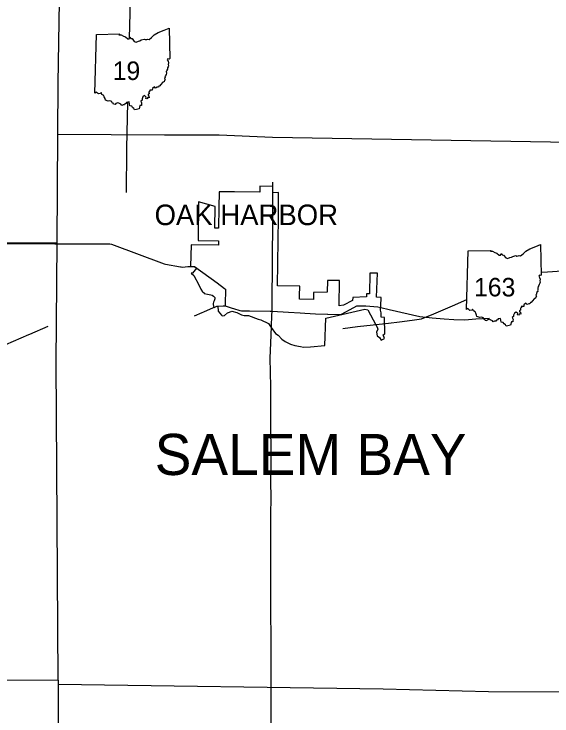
# Model space of a CAD drawing. Extents: x -232 to 448, y 619 to 1059.
# Drawn here: x 271.78 to 298.62, y 854.99 to 890 of the extents above; entities that cross this region are included whole.
import ezdxf

# ---------------------------------------------------------------- set-up
doc = ezdxf.new("R2010")
doc.units = 0
doc.layers.add('Default', color=7, linetype='Continuous')

msp = doc.modelspace()

# ---------------------------------------------------------------- linework, layer by layer
at = {"layer": 'Default'}
for p, q in [((275.817, 886.053), (275.899, 888.982)), ((275.817, 886.053), (275.899, 888.982)), ((284.048, 881.405), (284.047, 881.111)), ((284.697, 881.399), (284.048, 881.405)), ((280.977, 880.636), (280.973, 878.696)), ((281.81, 880.401), (280.977, 880.636)), ((281.804, 879.324), (281.81, 880.401)), ((281.986, 879.323), (281.804, 879.324)), ((280.973, 878.696), (281.983, 878.692)), ((280.621, 878.48), (280.591, 877.406)), ((294.349, 875.26), (294.431, 878.189)), ((294.349, 875.26), (294.431, 878.189)), ((280.891, 877.328), (280.692, 877.07))]:
    msp.add_line(p, q, dxfattribs=at)
for points in [[(273.973, 884.01), (273.991, 886.54), (274.111, 894.733), (274.2, 900.175), (274.21, 900.311), (274.401, 911.082), (274.524, 918.377)], [(277.536, 888.796), (277.606, 891.306), (277.607, 891.375), (277.67, 896.738), (277.671, 896.823), (277.644, 899.424), (277.643, 899.47)], [(275.899, 888.982), (277.036, 889.001), (277.018, 888.966), (277.125, 888.958), (277.239, 888.896), (277.335, 888.856), (277.453, 888.763), (277.524, 888.764), (277.554, 888.84), (277.608, 888.781), (277.672, 888.771), (277.782, 888.631), (277.874, 888.6), (277.983, 888.648), (278.065, 888.656), (278.125, 888.704), (278.281, 888.744), (278.325, 888.72), (278.407, 888.725), (278.449, 888.743), (278.521, 888.727), (278.647, 888.833), (278.778, 888.959), (278.979, 889.077), (279.278, 889.19), (279.515, 889.29), (279.55, 887.77)], [(275.899, 888.982), (277.036, 889.001), (277.018, 888.966), (277.125, 888.958), (277.239, 888.896), (277.335, 888.856), (277.453, 888.763), (277.524, 888.764), (277.554, 888.84), (277.608, 888.781), (277.672, 888.771), (277.782, 888.631), (277.874, 888.6), (277.983, 888.648), (278.065, 888.656), (278.125, 888.704), (278.281, 888.744), (278.325, 888.72), (278.407, 888.725), (278.449, 888.743), (278.521, 888.727), (278.647, 888.833), (278.778, 888.959), (278.979, 889.077), (279.278, 889.19), (279.515, 889.29), (279.55, 887.77)], [(279.55, 887.77), (279.515, 887.749), (279.46, 887.759), (279.424, 887.716), (279.469, 887.645), (279.49, 887.57), (279.471, 887.487), (279.49, 887.419), (279.477, 887.362), (279.443, 887.305), (279.431, 887.25), (279.402, 887.193), (279.405, 887.161), (279.377, 887.136), (279.382, 887.041), (279.368, 886.988), (279.373, 886.943), (279.328, 886.931), (279.338, 886.893), (279.309, 886.864), (279.315, 886.814), (279.283, 886.783), (279.315, 886.719), (279.289, 886.699), (279.268, 886.621), (279.211, 886.605), (279.095, 886.464), (279.054, 886.41), (279.008, 886.397), (278.983, 886.341), (278.927, 886.341), (278.841, 886.303), (278.786, 886.369), (278.689, 886.29), (278.678, 886.198), (278.556, 886.201), (278.561, 886.155), (278.534, 886.142), (278.509, 886.095), (278.523, 886.013), (278.466, 885.992), (278.473, 885.945), (278.51, 885.915), (278.526, 885.824), (278.465, 885.843), (278.415, 885.766), (278.364, 885.784), (278.381, 885.849), (278.294, 885.927), (278.212, 885.865), (278.17, 885.764), (278.169, 885.697), (278.108, 885.656), (278.147, 885.561), (278.14, 885.495), (278.141, 885.433), (278.065, 885.435), (278.019, 885.267)], [(279.55, 887.77), (279.515, 887.749), (279.46, 887.759), (279.424, 887.716), (279.469, 887.645), (279.49, 887.57), (279.471, 887.487), (279.49, 887.419), (279.477, 887.362), (279.443, 887.305), (279.431, 887.25), (279.402, 887.193), (279.405, 887.161), (279.377, 887.136), (279.382, 887.041), (279.368, 886.988), (279.373, 886.943), (279.328, 886.931), (279.338, 886.893), (279.309, 886.864), (279.315, 886.814), (279.283, 886.783), (279.315, 886.719), (279.289, 886.699), (279.268, 886.621), (279.211, 886.605), (279.095, 886.464), (279.054, 886.41), (279.008, 886.397), (278.983, 886.341), (278.927, 886.341), (278.841, 886.303), (278.786, 886.369), (278.689, 886.29), (278.678, 886.198), (278.556, 886.201), (278.561, 886.155), (278.534, 886.142), (278.509, 886.095), (278.523, 886.013), (278.466, 885.992), (278.473, 885.945), (278.51, 885.915), (278.526, 885.824), (278.465, 885.843), (278.415, 885.766), (278.364, 885.784), (278.381, 885.849), (278.294, 885.927), (278.212, 885.865), (278.17, 885.764), (278.169, 885.697), (278.108, 885.656), (278.147, 885.561), (278.14, 885.495), (278.141, 885.433), (278.065, 885.435), (278.019, 885.267)], [(278.019, 885.267), (277.886, 885.235), (277.794, 885.216), (277.762, 885.292), (277.696, 885.332), (277.653, 885.409), (277.558, 885.42), (277.536, 885.525), (277.525, 885.611), (277.396, 885.59), (277.361, 885.537), (277.315, 885.523), (277.288, 885.471), (277.226, 885.466), (277.159, 885.441), (277.115, 885.493), (277.005, 885.545), (276.956, 885.572), (276.852, 885.53), (276.83, 885.481), (276.748, 885.503), (276.729, 885.558), (276.679, 885.574), (276.668, 885.632), (276.562, 885.664), (276.48, 885.651), (276.337, 885.698), (276.328, 885.775), (276.279, 885.868), (276.254, 885.933), (276.163, 885.983), (276.145, 886.06), (276.116, 886.058), (276.089, 886.027), (275.988, 886.012), (275.948, 886.044), (275.892, 886.098), (275.817, 886.053)], [(278.019, 885.267), (277.886, 885.235), (277.794, 885.216), (277.762, 885.292), (277.696, 885.332), (277.653, 885.409), (277.558, 885.42), (277.536, 885.525), (277.525, 885.611), (277.396, 885.59), (277.361, 885.537), (277.315, 885.523), (277.288, 885.471), (277.226, 885.466), (277.159, 885.441), (277.115, 885.493), (277.005, 885.545), (276.956, 885.572), (276.852, 885.53), (276.83, 885.481), (276.748, 885.503), (276.729, 885.558), (276.679, 885.574), (276.668, 885.632), (276.562, 885.664), (276.48, 885.651), (276.337, 885.698), (276.328, 885.775), (276.279, 885.868), (276.254, 885.933), (276.163, 885.983), (276.145, 886.06), (276.116, 886.058), (276.089, 886.027), (275.988, 886.012), (275.948, 886.044), (275.892, 886.098), (275.817, 886.053)], [(277.398, 881.098), (277.41, 883.221), (277.41, 883.292), (277.452, 885.599)], [(273.933, 878.589), (273.973, 884.01)], [(273.973, 884.01), (279.293, 883.973), (282.013, 883.967), (284.683, 883.859), (306.452, 883.484)], [(284.698, 881.398), (284.699, 881.614)], [(282.023, 881.125), (281.995, 880.342)], [(282.777, 881.122), (282.023, 881.125)], [(284.047, 881.111), (282.777, 881.122)], [(284.689, 879.832), (284.689, 879.837), (284.696, 881.128)], [(284.928, 876.433), (284.979, 879.831), (284.977, 881.1), (284.696, 881.083), (284.697, 881.399)], [(284.696, 881.128), (284.698, 881.398)], [(281.995, 880.342), (281.986, 879.323)], [(284.66, 875.561), (284.689, 879.733), (284.689, 879.832)], [(240.982, 878.692), (246.674, 878.656), (273.933, 878.589)], [(281.983, 878.692), (281.982, 878.474)], [(268.435, 878.575), (268.462, 878.574), (273.825, 878.539), (273.836, 878.539)], [(273.836, 878.539), (273.911, 878.537), (276.565, 878.528), (276.639, 878.527), (279.278, 877.542), (279.333, 877.521), (280.08, 877.393), (280.125, 877.385)], [(273.979, 856.774), (273.889, 872.62), (273.933, 878.589)], [(281.982, 878.474), (280.621, 878.48)], [(294.431, 878.189), (295.567, 878.208), (295.549, 878.173), (295.657, 878.165), (295.77, 878.103), (295.867, 878.063), (295.985, 877.97), (296.055, 877.971), (296.085, 878.048), (296.139, 877.989), (296.203, 877.978), (296.314, 877.838), (296.405, 877.808), (296.515, 877.856), (296.597, 877.864), (296.656, 877.911), (296.812, 877.952), (296.856, 877.927), (296.938, 877.932), (296.98, 877.95), (297.052, 877.934), (297.179, 878.041), (297.309, 878.166), (297.51, 878.285), (297.81, 878.397), (298.047, 878.497), (298.081, 876.977)], [(294.431, 878.189), (295.567, 878.208), (295.549, 878.173), (295.657, 878.165), (295.77, 878.103), (295.867, 878.063), (295.985, 877.97), (296.055, 877.971), (296.085, 878.048), (296.139, 877.989), (296.203, 877.978), (296.314, 877.838), (296.405, 877.808), (296.515, 877.856), (296.597, 877.864), (296.656, 877.911), (296.812, 877.952), (296.856, 877.927), (296.938, 877.932), (296.98, 877.95), (297.052, 877.934), (297.179, 878.041), (297.309, 878.166), (297.51, 878.285), (297.81, 878.397), (298.047, 878.497), (298.081, 876.977)], [(298.078, 877.118), (298.397, 877.137), (299.601, 877.224), (300.965, 877.397), (301.903, 877.516), (303.294, 877.506), (305.081, 877.449), (305.907, 877.436), (306.891, 877.597), (308.158, 877.77), (309.088, 877.934), (309.866, 878.062), (310.944, 878.031), (312.431, 877.934), (313.078, 877.869), (313.147, 877.862), (313.956, 877.943), (314.053, 877.953), (315.885, 878.144), (315.952, 878.15), (317.947, 878.338), (317.947, 878.338), (318.038, 878.346)], [(280.125, 877.385), (280.18, 877.375), (280.445, 877.398)], [(280.445, 877.398), (280.45, 877.399), (280.536, 877.406), (280.699, 877.405), (280.787, 877.404), (281.908, 876.584)], [(280.591, 877.406), (280.787, 877.404)], [(280.787, 877.404), (280.891, 877.328)], [(280.692, 877.07), (280.662, 877.08), (280.658, 877.078), (280.62, 877.08)], [(280.62, 877.08), (280.754, 876.959)], [(280.754, 876.959), (280.997, 876.492), (281.103, 876.271), (281.187, 876.147), (281.205, 876.124), (281.255, 876.107)], [(289.284, 875.273), (289.428, 875.236), (289.832, 874.496), (289.889, 874.379), (289.934, 874.278), (289.857, 874.134), (289.899, 873.947), (290.018, 873.866), (290.101, 873.732), (290.256, 873.817), (290.191, 873.997), (290.28, 874.048), (290.261, 874.858), (290.091, 874.88), (290.096, 875.1), (290.055, 875.228), (290.077, 875.452), (290.101, 875.865), (289.865, 875.874), (289.905, 877.074), (289.529, 877.073), (289.514, 876.038), (289.368, 876.049), (289.359, 875.885), (288.677, 875.867), (288.67, 875.713), (288.225, 875.478), (287.995, 875.45), (288.013, 876.705), (287.415, 876.702), (287.407, 876.129)], [(298.081, 876.977), (298.046, 876.956), (297.992, 876.966), (297.955, 876.923), (298, 876.852), (298.022, 876.777), (298.003, 876.694), (298.021, 876.626), (298.009, 876.569), (297.974, 876.512), (297.963, 876.458), (297.934, 876.401), (297.936, 876.369), (297.908, 876.343), (297.913, 876.248), (297.899, 876.196), (297.904, 876.15), (297.859, 876.138), (297.869, 876.101), (297.841, 876.072), (297.847, 876.022), (297.814, 875.99), (297.846, 875.926), (297.821, 875.906), (297.8, 875.828), (297.742, 875.813), (297.626, 875.671), (297.585, 875.617), (297.54, 875.604), (297.514, 875.549), (297.458, 875.548), (297.373, 875.51), (297.318, 875.576), (297.221, 875.497), (297.21, 875.406), (297.087, 875.409), (297.092, 875.362), (297.065, 875.349), (297.04, 875.303), (297.054, 875.22), (296.997, 875.2), (297.004, 875.152), (297.041, 875.123), (297.057, 875.031), (296.996, 875.05), (296.946, 874.973), (296.895, 874.991), (296.912, 875.056), (296.825, 875.134), (296.744, 875.072), (296.701, 874.972), (296.7, 874.904), (296.639, 874.863), (296.678, 874.768), (296.671, 874.703), (296.672, 874.64), (296.596, 874.642), (296.55, 874.474)], [(298.081, 876.977), (298.046, 876.956), (297.992, 876.966), (297.955, 876.923), (298, 876.852), (298.022, 876.777), (298.003, 876.694), (298.021, 876.626), (298.009, 876.569), (297.974, 876.512), (297.963, 876.458), (297.934, 876.401), (297.936, 876.369), (297.908, 876.343), (297.913, 876.248), (297.899, 876.196), (297.904, 876.15), (297.859, 876.138), (297.869, 876.101), (297.841, 876.072), (297.847, 876.022), (297.814, 875.99), (297.846, 875.926), (297.821, 875.906), (297.8, 875.828), (297.742, 875.813), (297.626, 875.671), (297.585, 875.617), (297.54, 875.604), (297.514, 875.549), (297.458, 875.548), (297.373, 875.51), (297.318, 875.576), (297.221, 875.497), (297.21, 875.406), (297.087, 875.409), (297.092, 875.362), (297.065, 875.349), (297.04, 875.303), (297.054, 875.22), (296.997, 875.2), (297.004, 875.152), (297.041, 875.123), (297.057, 875.031), (296.996, 875.05), (296.946, 874.973), (296.895, 874.991), (296.912, 875.056), (296.825, 875.134), (296.744, 875.072), (296.701, 874.972), (296.7, 874.904), (296.639, 874.863), (296.678, 874.768), (296.671, 874.703), (296.672, 874.64), (296.596, 874.642), (296.55, 874.474)], [(281.908, 876.584), (282.274, 876.316), (282.333, 876.273), (282.314, 875.515), (282.314, 875.515), (282.312, 875.45)], [(287.407, 876.129), (286.722, 876.105), (286.727, 875.95), (286.727, 875.763), (286.028, 875.776), (286.014, 875.948), (286.038, 876.432), (284.928, 876.433)], [(281.255, 876.107), (281.271, 876.067), (281.599, 875.995), (281.66, 875.971), (281.733, 875.927), (281.79, 875.884), (281.803, 875.864), (281.791, 875.789), (281.76, 875.696), (281.729, 875.627), (281.713, 875.562), (281.715, 875.502), (281.732, 875.422), (281.763, 875.365)], [(284.649, 874.965), (284.658, 875.183), (284.66, 875.561)], [(288.186, 874.318), (288.914, 874.408), (289.696, 874.494), (290.454, 874.585), (291.017, 874.65), (291.635, 874.723), (292.101, 874.788), (292.73, 875.044), (293.662, 875.448), (294.363, 875.764)], [(280.786, 874.948), (281.168, 875.116), (281.25, 875.152), (281.73, 875.353)], [(281.73, 875.353), (281.8, 875.382), (281.894, 875.421), (281.932, 875.424)], [(281.763, 875.365), (281.894, 875.421), (281.948, 875.425), (281.958, 875.186), (282.124, 874.978), (282.167, 874.949), (282.274, 874.969), (282.427, 875.1), (282.528, 875.134), (282.643, 875.175), (282.895, 875.112), (283.127, 874.996), (283.259, 874.965), (283.485, 874.966), (283.965, 874.774), (284.1, 874.749), (284.471, 874.562), (284.608, 874.356), (284.825, 874.069), (284.952, 873.974), (285.144, 873.788), (285.31, 873.67), (285.581, 873.531), (285.79, 873.466), (286.078, 873.414), (286.228, 873.39), (286.575, 873.405), (287.285, 873.458)], [(281.932, 875.424), (282.219, 875.444), (282.219, 875.444), (282.312, 875.45)], [(282.312, 875.45), (282.671, 875.328), (282.736, 875.306), (283.049, 875.219), (283.133, 875.195), (283.301, 875.192)], [(283.301, 875.192), (283.458, 875.188), (283.528, 875.187), (284.558, 875.183), (284.557, 875.183), (284.658, 875.183)], [(284.658, 875.183), (285.471, 875.132), (286.051, 875.096), (286.283, 875.082)], [(287.335, 874.826), (289.284, 875.273)], [(287.419, 875.032), (287.441, 875.031), (287.945, 875.019), (288.118, 875.036), (288.731, 875.361), (288.89, 875.449), (289.337, 875.452), (289.935, 875.388), (290.072, 875.356)], [(290.072, 875.356), (290.498, 875.258), (292.02, 874.907), (292.635, 874.838), (293.241, 874.79), (293.724, 874.76), (294.264, 874.753), (294.816, 874.791), (295.482, 874.834), (295.487, 874.834)], [(296.55, 874.474), (296.417, 874.442), (296.325, 874.423), (296.293, 874.499), (296.227, 874.54), (296.184, 874.616), (296.09, 874.627), (296.067, 874.733), (296.057, 874.818), (295.927, 874.797), (295.892, 874.745), (295.846, 874.731), (295.82, 874.678), (295.757, 874.673), (295.69, 874.649), (295.646, 874.7), (295.536, 874.752), (295.487, 874.779), (295.384, 874.737), (295.362, 874.688), (295.279, 874.71), (295.26, 874.765), (295.21, 874.781), (295.199, 874.84), (295.093, 874.871), (295.012, 874.858), (294.868, 874.905), (294.859, 874.982), (294.811, 875.076), (294.785, 875.141), (294.694, 875.19), (294.676, 875.267), (294.647, 875.265), (294.621, 875.234), (294.52, 875.219), (294.48, 875.251), (294.423, 875.305), (294.349, 875.26)], [(296.55, 874.474), (296.417, 874.442), (296.325, 874.423), (296.293, 874.499), (296.227, 874.54), (296.184, 874.616), (296.09, 874.627), (296.067, 874.733), (296.057, 874.818), (295.927, 874.797), (295.892, 874.745), (295.846, 874.731), (295.82, 874.678), (295.757, 874.673), (295.69, 874.649), (295.646, 874.7), (295.536, 874.752), (295.487, 874.779), (295.384, 874.737), (295.362, 874.688), (295.279, 874.71), (295.26, 874.765), (295.21, 874.781), (295.199, 874.84), (295.093, 874.871), (295.012, 874.858), (294.868, 874.905), (294.859, 874.982), (294.811, 875.076), (294.785, 875.141), (294.694, 875.19), (294.676, 875.267), (294.647, 875.265), (294.621, 875.234), (294.52, 875.219), (294.48, 875.251), (294.423, 875.305), (294.349, 875.26)], [(284.628, 874.422), (284.649, 874.965)], [(286.283, 875.082), (286.824, 875.049), (287.419, 875.032)], [(287.285, 873.458), (287.335, 874.826)], [(271.377, 873.512), (272.52, 874.008), (272.576, 874.032), (273.484, 874.431)], [(284.61, 873.987), (284.628, 874.422)], [(284.593, 871.268), (284.592, 871.41), (284.577, 872.143), (284.565, 872.84), (284.61, 873.987)], [(284.602, 856.424), (284.605, 857.294), (284.61, 858.054), (284.606, 858.667), (284.603, 859.171), (284.599, 859.861), (284.592, 860.647), (284.588, 861.295), (284.587, 861.935), (284.592, 862.625), (284.595, 863.44), (284.6, 864.238), (284.596, 865.041), (284.605, 865.876), (284.6, 866.683), (284.605, 867.432), (284.604, 868.368), (284.6, 869.247), (284.595, 869.881), (284.594, 870.696), (284.593, 871.268)], [(241.086, 856.841), (246.842, 856.866), (255.063, 856.795), (273.979, 856.774)], [(273.981, 856.583), (273.991, 851.155), (273.816, 840.668)], [(273.979, 856.774), (273.981, 856.583)], [(273.981, 856.583), (290.19, 856.341), (295.448, 856.203), (300.895, 856.201), (306.219, 856.122)], [(287.247, 851.805), (287.244, 851.92), (287.247, 852.372), (287.245, 852.809), (287.243, 853.266), (287.244, 853.698), (287.166, 853.673), (286.866, 853.688), (286.447, 853.698), (286.03, 853.705), (285.384, 853.719), (284.579, 853.738), (284.606, 854.384), (284.609, 854.825), (284.609, 855.28), (284.608, 855.913), (284.602, 856.424)]]:
    msp.add_lwpolyline(points, dxfattribs=at)

# ---------------------------------------------------------------- texts
for s, height, p in [('19', 0.9234, (276.703, 886.706)), ('OAK HARBOR', 1.026, (278.794, 879.468)), ('163', 0.9234, (294.729, 875.913)), ('SALEM BAY', 2.052, (278.799, 867.007))]:
    msp.add_text(s, height=height, dxfattribs=at).set_placement(p)

doc.saveas('drawing.dxf')
